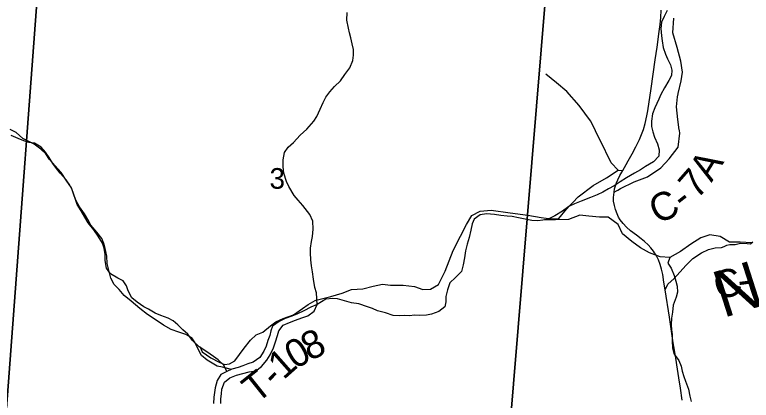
# Model space of a CAD drawing. Extents: x 0 to 34, y 0 to 22.
# Drawn here: x 3.758 to 5.252, y 18.512 to 19.293 of the extents above; entities that cross this region are included whole.
import ezdxf

# ---------------------------------------------------------------- set-up
doc = ezdxf.new("R2010")
doc.units = 0
for name, color, linetype in [('GM_X_Corporation', 7, 'Continuous'), ('GM_X_County_Road', 7, 'Continuous'), ('GM_X_County_Road_Text', 7, 'Continuous'), ('GM_X_Major_River', 7, 'Continuous'), ('GM_X_Minor_River', 7, 'Continuous'), ('GM_X_Minor_River_Text', 7, 'Continuous'), ('GM_X_Section_Text', 7, 'Continuous'), ('GM_X_State_Route', 7, 'Continuous'), ('GM_X_Township_Road', 7, 'Continuous'), ('GM_X_Township_Road_Text', 7, 'Continuous')]:
    doc.layers.add(name, color=color, linetype=linetype)

msp = doc.modelspace()

# ---------------------------------------------------------------- linework, layer by layer
at = {"layer": 'GM_X_Corporation'}
for points in [[(2.8266, 19.5815), (3.8179, 19.5177), (3.742, 18.4953), (2.7366, 18.558)], [(3.8179, 19.5177), (4.8445, 19.4512), (4.7598, 18.4308), (3.742, 18.4953)], [(4.8445, 19.4512), (5.8355, 19.3781), (5.775, 18.3681), (4.7598, 18.4308)]]:
    msp.add_lwpolyline(points, close=True, dxfattribs=at)
at = {"layer": 'GM_X_County_Road'}
for points in [[(5.1036, 19.1337), (5.1095, 19.1595), (5.1123, 19.177), (5.109, 19.1994), (5.1012, 19.2268), (5.0923, 19.2568), (5.0948, 19.2864)], [(5.1057, 19.0602), (5.1029, 19.0813), (5.1001, 19.1068), (5.1021, 19.1273), (5.1034, 19.1329), (5.1036, 19.1337)], [(4.9808, 18.9376), (4.9863, 18.9415), (5.0141, 18.9546), (5.0415, 18.9647), (5.0682, 18.9831), (5.085, 19.0016), (5.1033, 19.0247), (5.1065, 19.0535), (5.1059, 19.0586), (5.1057, 19.0602)], [(4.9734, 18.9337), (4.9787, 18.9362), (4.9808, 18.9376)], [(5.0771, 18.7359), (5.0824, 18.747), (5.095, 18.7591), (5.1188, 18.7855), (5.1332, 18.7995), (5.151, 18.8107), (5.1651, 18.8176), (5.1786, 18.8207), (5.1914, 18.8217), (5.1968, 18.8236), (5.2023, 18.8266), (5.208, 18.8277), (5.2189, 18.8279), (5.2297, 18.8303), (5.2433, 18.8296), (5.2497, 18.8294), (5.2548, 18.833)]]:
    msp.add_lwpolyline(points, dxfattribs=at)
at = {"layer": 'GM_X_Major_River'}
for points in [[(5.0809, 19.3018), (5.0748, 19.29), (5.0699, 19.2786), (5.0684, 19.2657), (5.0699, 19.2506), (5.0707, 19.2407), (5.0729, 19.2274), (5.0775, 19.2138), (5.0816, 19.2039), (5.088, 19.1922), (5.0903, 19.1812), (5.0896, 19.1702), (5.0843, 19.1599), (5.0759, 19.1455), (5.0684, 19.1318), (5.0642, 19.1223), (5.0559, 19.1049), (5.0514, 19.0924), (5.0491, 19.078), (5.0495, 19.0666), (5.0517, 19.0563), (5.0555, 19.045), (5.0616, 19.0321), (5.065, 19.0195), (5.0642, 19.007), (5.0532, 18.9956), (5.037, 18.9858), (5.0268, 18.9789), (5.015, 18.9721), (4.9984, 18.963), (4.9856, 18.9546), (4.9738, 18.9467), (4.9621, 18.9406), (4.9504, 18.9337), (4.9391, 18.9284), (4.9258, 18.9231), (4.9065, 18.9155), (4.8929, 18.9102), (4.882, 18.9045), (4.8687, 18.895), (4.8536, 18.8859), (4.8396, 18.8794), (4.8291, 18.8771), (4.8188, 18.8756), (4.8068, 18.8764), (4.7931, 18.879), (4.7795, 18.882), (4.7667, 18.8843), (4.7569, 18.8854), (4.7436, 18.8866), (4.7308, 18.8885), (4.7149, 18.8896), (4.7017, 18.8881), (4.6896, 18.8793), (4.6858, 18.8695), (4.6828, 18.8566), (4.6794, 18.8418), (4.6756, 18.8281), (4.6725, 18.8148), (4.6703, 18.8004), (4.6676, 18.7864)], [(4.6676, 18.7864), (4.6642, 18.7727), (4.6517, 18.7609), (4.6404, 18.7499), (4.6359, 18.7359), (4.6325, 18.7222), (4.6325, 18.7116), (4.6306, 18.7013), (4.6181, 18.6922), (4.6034, 18.6865), (4.5931, 18.6846), (4.5799, 18.6839), (4.569, 18.6842), (4.5587, 18.6831), (4.5489, 18.6835), (4.5387, 18.6831), (4.5255, 18.6838), (4.51, 18.6891), (4.4941, 18.6933), (4.4839, 18.6982), (4.4737, 18.7016), (4.4559, 18.7073), (4.4412, 18.7096), (4.4272, 18.7137), (4.4128, 18.7179), (4.403, 18.7183), (4.3894, 18.7168), (4.3713, 18.7061)], [(4.3713, 18.7061), (4.3584, 18.7004), (4.3444, 18.6932), (4.3319, 18.6871), (4.3199, 18.6826), (4.3066, 18.6776), (4.2945, 18.6719), (4.2813, 18.6624), (4.2779, 18.6529), (4.2756, 18.6431), (4.2718, 18.6328), (4.2681, 18.6214), (4.2635, 18.6116), (4.2552, 18.599), (4.2416, 18.5895), (4.231, 18.5861), (4.2212, 18.5819), (4.2113, 18.5781), (4.1989, 18.5751), (4.1887, 18.5701), (4.1762, 18.5641), (4.169, 18.5523), (4.1648, 18.5371), (4.1618, 18.5181), (4.1611, 18.5056)], [(4.1766, 18.5052), (4.1766, 18.5151), (4.1777, 18.525), (4.1781, 18.5345), (4.1834, 18.5489), (4.1947, 18.5576), (4.2079, 18.5626), (4.2208, 18.5664), (4.2336, 18.5694), (4.2469, 18.5717), (4.259, 18.5804), (4.2696, 18.5933), (4.276, 18.6044), (4.2832, 18.618), (4.287, 18.6306), (4.2911, 18.6435), (4.2941, 18.6529), (4.3028, 18.6643), (4.3157, 18.6697), (4.3274, 18.6742), (4.3406, 18.6788), (4.3527, 18.683), (4.3652, 18.6925), (4.3713, 18.7061)]]:
    msp.add_lwpolyline(points, dxfattribs=at)
at = {"layer": 'GM_X_Minor_River'}
for points in [[(4.3713, 18.7061), (4.3705, 18.73), (4.3671, 18.7403), (4.3641, 18.7573), (4.3618, 18.7725), (4.3599, 18.7847), (4.3588, 18.7964), (4.3581, 18.8108), (4.3581, 18.8203), (4.3599, 18.8336), (4.3618, 18.8439), (4.3637, 18.8587), (4.363, 18.875), (4.3566, 18.8883), (4.3422, 18.9065), (4.3328, 18.9175), (4.3252, 18.9273), (4.3142, 18.9451), (4.3093, 18.9554), (4.3037, 18.9725), (4.3025, 18.985), (4.3025, 18.9994), (4.3056, 19.0142), (4.3131, 19.0252), (4.3233, 19.0343), (4.3369, 19.0495), (4.3509, 19.0616), (4.3645, 19.0776), (4.371, 19.0874), (4.3778, 19.1019), (4.3834, 19.1155), (4.3891, 19.1265), (4.3971, 19.1375), (4.4065, 19.1482), (4.4186, 19.1596), (4.4277, 19.1721), (4.4375, 19.1861), (4.4436, 19.2005), (4.4455, 19.2112), (4.4451, 19.2233), (4.4428, 19.2347), (4.4398, 19.2468), (4.4371, 19.2571), (4.4353, 19.2665), (4.4319, 19.2825), (4.4322, 19.298)], [(4.1976, 18.5745), (4.1797, 18.5793), (4.1691, 18.5812), (4.1585, 18.587), (4.1487, 18.5931), (4.137, 18.603), (4.1306, 18.6155), (4.1242, 18.6284), (4.1178, 18.6387), (4.1053, 18.6452), (4.091, 18.6498), (4.0755, 18.6556), (4.06, 18.6643), (4.043, 18.6754), (4.0275, 18.6857), (4.0124, 18.6983), (3.9946, 18.7128), (3.9806, 18.7242), (3.9701, 18.7368), (3.9603, 18.7467), (3.9535, 18.7592), (3.946, 18.7892), (3.9449, 18.804), (3.9419, 18.8196), (3.9393, 18.8295), (3.9348, 18.8397), (3.9246, 18.853), (3.9125, 18.8667), (3.9069, 18.8785), (3.8997, 18.8899), (3.8899, 18.904), (3.8824, 18.9173), (3.8782, 18.9291), (3.8737, 18.9424), (3.8643, 18.9561), (3.8526, 18.9736), (3.8405, 18.9869), (3.8292, 18.9998), (3.8217, 19.0116), (3.8111, 19.0212), (3.7979, 19.0311), (3.7846, 19.0376), (3.7748, 19.0425), (3.7616, 19.0547), (3.7491, 19.0608)], [(4.1887, 18.5701), (4.1826, 18.5834), (4.1709, 18.594), (4.1611, 18.6009), (4.1478, 18.61), (4.1324, 18.6206), (4.1191, 18.6331), (4.1093, 18.646), (4.0995, 18.6547), (4.0893, 18.6646), (4.0794, 18.6729), (4.0696, 18.6786), (4.0549, 18.6835), (4.0435, 18.6885), (4.0299, 18.6964), (4.0201, 18.7017), (4.0065, 18.7108), (3.9959, 18.7199), (3.9884, 18.7336), (3.9853, 18.7442), (3.9782, 18.7541), (3.9672, 18.7598), (3.9528, 18.7685), (3.9445, 18.7799), (3.9419, 18.795), (3.9415, 18.8072), (3.94, 18.8201), (3.9362, 18.8307), (3.9275, 18.8447), (3.9188, 18.8572), (3.9075, 18.8717), (3.9003, 18.8834), (3.8931, 18.8963), (3.8852, 18.9085), (3.8814, 18.9191), (3.878, 18.9286), (3.8746, 18.9384), (3.8701, 18.9479), (3.8629, 18.9589), (3.8508, 18.9722), (3.8429, 18.982), (3.8357, 18.9919), (3.8285, 19.0044), (3.8206, 19.0147), (3.8119, 19.0253), (3.7983, 19.0332), (3.7877, 19.0347), (3.7771, 19.0378), (3.7654, 19.0423), (3.751, 19.0488)], [(5.2527, 18.8311), (5.2292, 18.8323), (5.2072, 18.8323), (5.1887, 18.8437), (5.1679, 18.8475), (5.149, 18.8415), (5.1289, 18.8286), (5.1084, 18.8134), (5.0868, 18.8016), (5.0671, 18.8027), (5.0452, 18.8111), (5.027, 18.821), (5.0093, 18.8336), (4.9907, 18.8492), (4.9817, 18.8683), (4.9617, 18.8831), (4.9439, 18.8831), (4.9223, 18.885), (4.9041, 18.8873), (4.8808, 18.8786), (4.8291, 18.8771)], [(5.0868, 18.8016), (5.0823, 18.79), (5.0895, 18.7798), (5.0955, 18.7646), (5.0985, 18.7532), (5.1012, 18.743), (5.1019, 18.7308), (5.0993, 18.721), (5.0932, 18.7046), (5.0917, 18.6906), (5.0902, 18.6781), (5.0891, 18.6659), (5.0902, 18.6549), (5.091, 18.6451), (5.091, 18.6321), (5.0917, 18.6185), (5.0951, 18.6056), (5.1046, 18.5927), (5.1098, 18.5813), (5.1117, 18.5711), (5.1151, 18.5604), (5.1182, 18.5509), (5.1246, 18.5342), (5.1268, 18.5206), (5.1299, 18.5092)]]:
    msp.add_lwpolyline(points, dxfattribs=at)
at = {"layer": 'GM_X_State_Route'}
msp.add_lwpolyline([(5.1118, 18.5119), (5.1082, 18.5365), (5.1048, 18.5574), (5.1019, 18.5751), (5.0984, 18.5976), (5.0961, 18.6136), (5.0935, 18.6282), (5.0856, 18.6804), (5.0771, 18.7359), (5.0746, 18.7517), (5.072, 18.7672), (5.0695, 18.7775), (5.0666, 18.7875), (5.0633, 18.7968), (5.0602, 18.8035), (5.0573, 18.8084), (5.0557, 18.811), (5.0532, 18.8142), (5.0483, 18.8207), (5.0429, 18.827), (5.0353, 18.8341), (5.0286, 18.8395), (5.0192, 18.8464), (5.0067, 18.8556), (4.9986, 18.8627), (4.992, 18.87), (4.9861, 18.8774), (4.9826, 18.8831), (4.9795, 18.8901), (4.9763, 18.8989), (4.9742, 18.9067), (4.9726, 18.9159), (4.9725, 18.9231), (4.9734, 18.9337), (4.9746, 18.9403), (4.9753, 18.9428), (4.977, 18.9489), (4.9785, 18.953), (4.981, 18.9587), (4.9854, 18.9674), (4.9909, 18.9778), (4.9979, 18.9899), (5.002, 18.9972), (5.01, 19.0112), (5.0174, 19.0254), (5.0247, 19.0403), (5.0292, 19.0507), (5.0328, 19.061), (5.0365, 19.0729), (5.0401, 19.0885), (5.0419, 19.0985), (5.0485, 19.1438), (5.0568, 19.2021), (5.0605, 19.2279), (5.065, 19.2592), (5.067, 19.2739), (5.0685, 19.2876), (5.0689, 19.303)], dxfattribs=at)
at = {"layer": 'GM_X_Township_Road'}
for points in [[(4.9349, 19.0599), (4.9258, 19.0782), (4.9025, 19.1095), (4.8776, 19.1381), (4.8569, 19.1554), (4.835, 19.173)], [(4.9815, 18.9784), (4.9673, 18.9932), (4.9453, 19.039), (4.9366, 19.0564), (4.9349, 19.0599)], [(4.8896, 18.9126), (4.9005, 18.9245), (4.931, 18.9471), (4.958, 18.9629), (4.9815, 18.9784), (4.9909, 18.9778)], [(4.3694, 18.715), (4.399, 18.7221), (4.4225, 18.7291), (4.4412, 18.7362), (4.4643, 18.7376), (4.4852, 18.7436), (4.5042, 18.7473), (4.5201, 18.7453), (4.5459, 18.7455), (4.569, 18.7423), (4.586, 18.7365), (4.6012, 18.7372), (4.6176, 18.7469), (4.631, 18.7738), (4.6472, 18.8159), (4.6622, 18.8443), (4.6741, 18.8682), (4.6852, 18.8863), (4.702, 18.895), (4.724, 18.8975), (4.7626, 18.8919), (4.7987, 18.8875), (4.8259, 18.8824), (4.8456, 18.88), (4.8612, 18.8807), (4.8772, 18.8992), (4.8841, 18.9067), (4.8896, 18.9126)], [(4.134, 18.6211), (4.1385, 18.6104), (4.1562, 18.5978), (4.1732, 18.5889), (4.1835, 18.5847), (4.1941, 18.5858), (4.2044, 18.5922), (4.2235, 18.6175), (4.2365, 18.6338), (4.2476, 18.6447), (4.2616, 18.6503), (4.2769, 18.6628), (4.2879, 18.6711), (4.3028, 18.6778), (4.3237, 18.6853), (4.3416, 18.6977), (4.3534, 18.7064), (4.3676, 18.7141), (4.3694, 18.715)]]:
    msp.add_lwpolyline(points, dxfattribs=at)

# ---------------------------------------------------------------- texts
at = {"layer": 'GM_X_County_Road_Text'}
for s, rotation, p in [('A', 58.5244, (5.171, 18.9523)), ('7', 48.781, (5.1417, 18.9175)), ('C', 25.982, (5.0619, 18.8677)), ('-', 38.0577, (5.1149, 18.8951)), ('C', 15.5623, (5.1845, 18.7145)), ('-', 7.3477, (5.2274, 18.7266))]:
    msp.add_text(s, height=0.0568, rotation=rotation, dxfattribs=at).set_placement(p)
at = {"layer": 'GM_X_Minor_River_Text'}
msp.add_text('Norris', height=0.0947, rotation=17.7682, dxfattribs=at).set_placement((5.1944, 18.6783))
at = {"layer": 'GM_X_Section_Text'}
msp.add_text('3', height=0.0419, rotation=0, dxfattribs=at).set_placement((4.2751, 18.9407))
at = {"layer": 'GM_X_Township_Road_Text'}
for s, rotation, p in [('8', 26.0821, (4.3563, 18.5908)), ('0', 30.1268, (4.327, 18.5737)), ('1', 41.4992, (4.3032, 18.5522)), ('T', 38.755, (4.2487, 18.5039)), ('-', 46.5359, (4.2881, 18.5362))]:
    msp.add_text(s, height=0.0568, rotation=rotation, dxfattribs=at).set_placement(p)

doc.saveas('drawing.dxf')
